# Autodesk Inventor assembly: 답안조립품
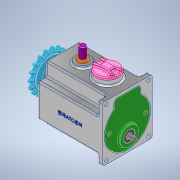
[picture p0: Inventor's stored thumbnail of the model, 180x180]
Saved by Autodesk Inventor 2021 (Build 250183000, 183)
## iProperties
Created: 2022-08
Part Number: 답안조립품
Document SubType Name: Assembly
Designer: Owner
Author: Owner
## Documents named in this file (16)
- C:\Users\Owner\Desktop\720810V1007\답안조립품.iam
- C:\Users\Owner\Desktop\720810V1007\본체.ipt
- C:\Users\Owner\Desktop\720810V1007\멈춤나사 M3.ipt
- C:\Users\Owner\Desktop\720810V1007\메인 축.ipt
- C:\Users\Owner\Desktop\720810V1007\베어링 608.ipt
- C:\Users\Owner\Desktop\720810V1007\베어링 6003.ipt
- C:\Users\Owner\Desktop\720810V1007\볼트 M4 x 10.ipt
- C:\Users\Owner\Desktop\720810V1007\부시.ipt
- C:\Users\Owner\Desktop\720810V1007\상부 캡.ipt
- C:\Users\Owner\Desktop\720810V1007\서브 축.ipt
- C:\Users\Owner\Desktop\720810V1007\스프로킷.ipt
- C:\Users\Owner\Desktop\720810V1007\슬라이더.ipt
- C:\Users\Owner\Desktop\720810V1007\오일 실 8 x 22 x 7.ipt
- C:\Users\Owner\Desktop\720810V1007\오일 실 17 x 32 x 8.ipt
- C:\Users\Owner\Desktop\720810V1007\커버.ipt
- C:\Users\Owner\Desktop\720810V1007\키 5 x 5.ipt
